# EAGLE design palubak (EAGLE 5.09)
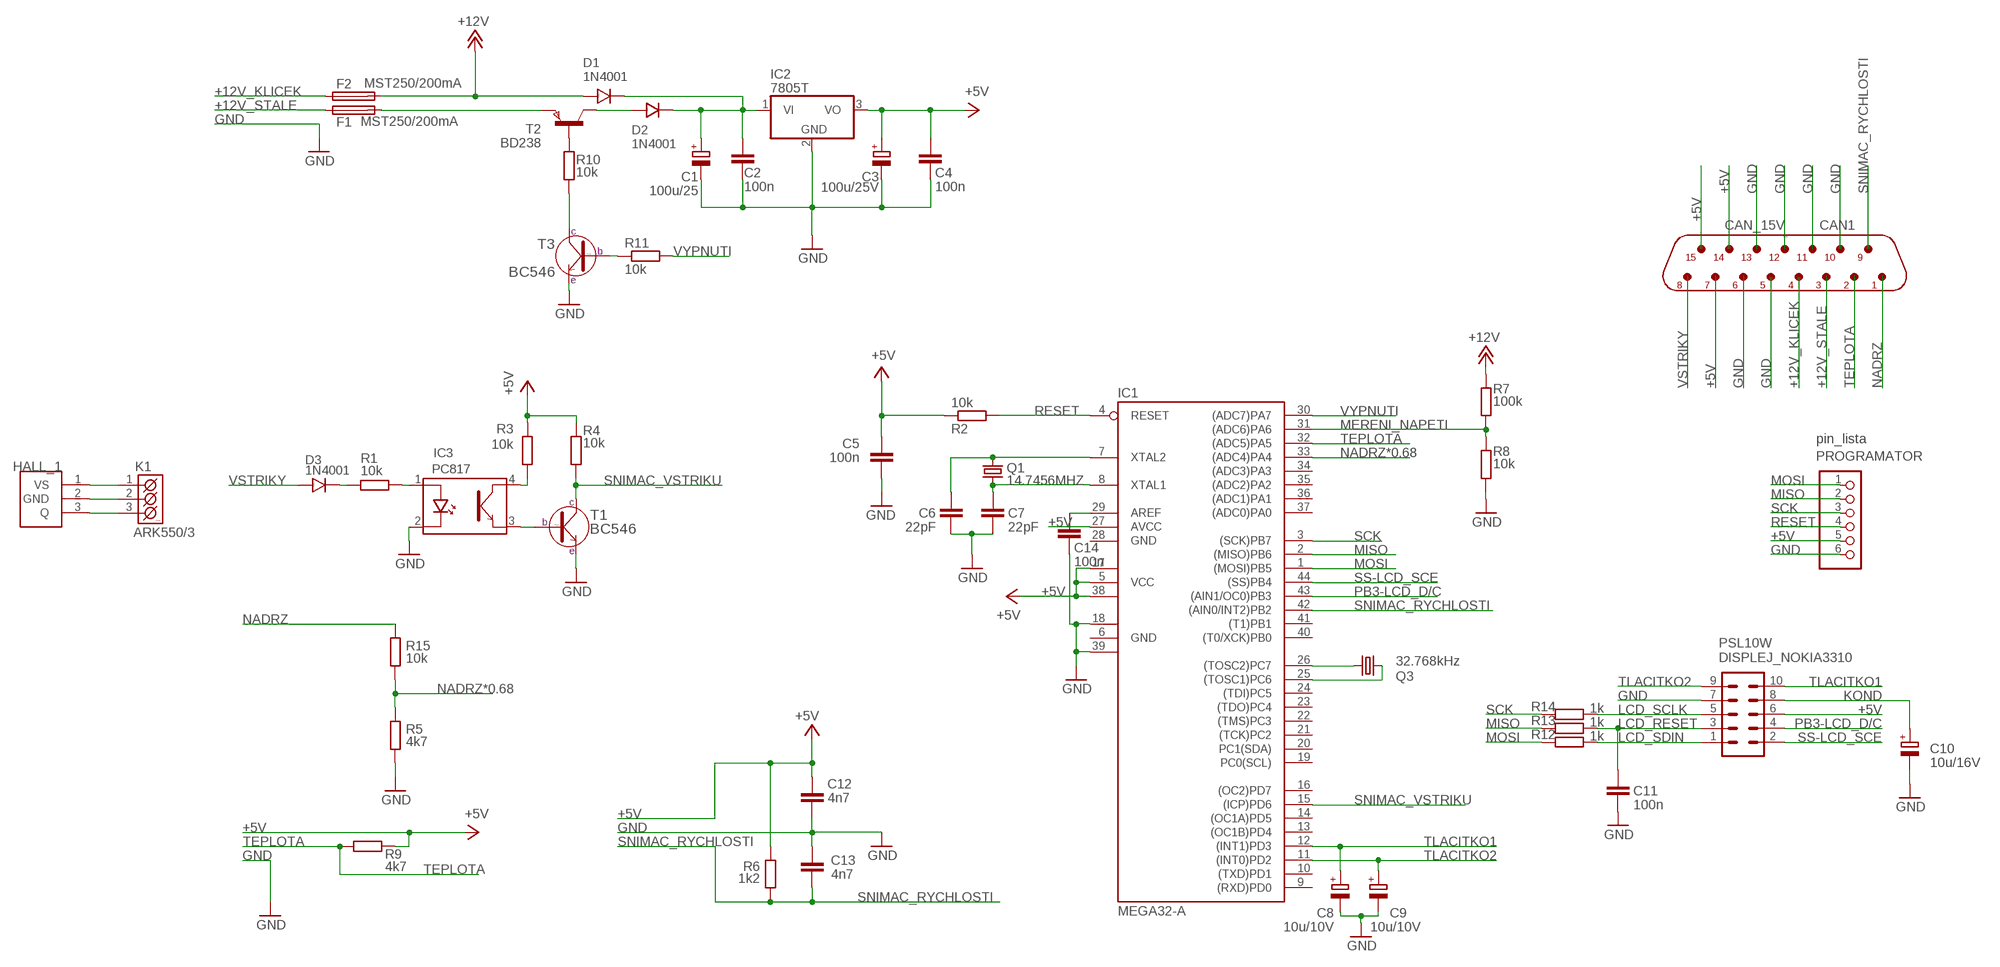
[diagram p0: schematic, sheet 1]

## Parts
C1  100u/25  CPOL-EUE3.5-8  [E3,5-8]
C2  100n  C-EUC1206  [C1206]
C3  100u/25V  CPOL-EUE3.5-8  [E3,5-8]
C4  100n  C-EUC1206  [C1206]
C5  100n  C-EUC1206  [C1206]
C6  22pF  C-EUC1206  [C1206]
C7  22pF  C-EUC1206  [C1206]
C8  10u/10V  CPOL-EUE2.5-6  [E2,5-6]
C9  10u/10V  CPOL-EUE2,5-6E  [E2,5-6E]
C10  10u/16V  CPOL-EUE2.5-6  [E2,5-6]
C11  100n  C-EUC1206  [C1206]
C12  4n7  C-EUC1206  [C1206]
C13  4n7  C-EUC1206  [C1206]
C14  100n  C-EUC1206  [C1206]
CAN1  CAN_15V  [CAN15V]
D1  1N4001  1N4007_SMD_SM-1  [SM-1]
D2  1N4001  1N4007_SMD_SM-1  [SM-1]
D3  1N4001  1N4007_SMD_SM-1  [SM-1]
DISPLEJ_NOKIA3310  PSL10W  10H  [10H]
F1  MST250/200mA  19560  [19560]
F2  MST250/200mA  19560  [19560]
HALL_1  TLE4905  [P-SSO-3-2]
IC1  MEGA32-A  [TQFP44]
IC2  7805T  [TO220H]
IC3  PC817  [DIL4]
K1  ARK550/3  [ARK550/3]
PROGRAMATOR  pin_lista  PINHD-1X6  [1X06]
Q1  14.7456MHZ  CRYTALHC49UP  [HC49UP@1]
Q3  32.768kHz  CRYSTALTC26H  [TC26H]
R1  10k  R-EU_M1206  [M1206]
R2  10k  R-EU_M1206  [M1206]
R3  10k  R-EU_M1206  [M1206]
R4  10k  R-EU_M1206  [M1206]
R5  4k7  R-EU_M1206  [M1206]
R6  1k2  R-EU_M1206  [M1206]
R7  100k  R-EU_M1206  [M1206]
R8  10k  R-EU_M1206  [M1206]
R9  4k7  R-EU_M1206  [M1206]
R10  10k  R-EU_M1206  [M1206]
R11  10k  R-EU_M1206  [M1206]
R12  1k  R-EU_M1206  [M1206]
R13  1k  R-EU_M1206  [M1206]
R14  1k  R-EU_M1206  [M1206]
R15  10k  R-EU_M1206  [M1206]
T1  BC546  [TO-92]
T2  BD238  [TO-126S]
T3  BC546  [TO-92]

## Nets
+5V: C3.+ C4.1 C5.2 C12.1 CAN1.7 CAN1.14 CAN1.15 DISPLEJ_NOKIA3310.6 IC1.5(VCC) IC1.17(VCC1) IC1.27(AVCC) IC1.38(VCC2) IC2.3(VO) PROGRAMATOR.5 R2.1 R3.1 R4.1 R6.1 R9.2
+12V: D1.A F2.2 R7.1
+12V_KLICEK: CAN1.4 F2.1
+12V_STALE: CAN1.3 F1.1
GND: C1.- C2.2 C3.- C4.2 C5.1 C6.2 C7.2 C8.- C9.- C10.- C11.2 C12.2 C13.1 C14.2 CAN1.5 CAN1.6 CAN1.10 CAN1.11 CAN1.12 CAN1.13 DISPLEJ_NOKIA3310.7 IC1.18(GND1) IC1.39(GND2) IC2.2(GND) IC3.2(K) PROGRAMATOR.6 R5.2 R8.2 T1.3(E) T3.3(E)
KOND: C10.+ DISPLEJ_NOKIA3310.8
LCD_RESET: C11.1 DISPLEJ_NOKIA3310.3 R13.1
LCD_SCLK: DISPLEJ_NOKIA3310.5 R14.1
LCD_SDIN: DISPLEJ_NOKIA3310.1 R12.1
MERENI_NAPETI: IC1.31((ADC6)PA6) R7.2 R8.1
MISO: IC1.2((MISO)PB6) PROGRAMATOR.2 R13.2
MOSI: IC1.1((MOSI)PB5) PROGRAMATOR.1 R12.2
N$1: C1.+ C2.1 D1.K D2.K IC2.1(VI)
N$2: D3.K R1.2
N$3: IC3.1(A) R1.1
N$4: IC3.4(C) R3.2
N$5: IC3.3(E) T1.2(B)
N$6: IC1.26((TOSC2)PC7) Q3.2
N$7: D2.A T2.2(C)
N$8: HALL_1.1(VS) K1.1(K1)
N$9: IC1.25((TOSC1)PC6) Q3.1
N$10: HALL_1.2(GND) K1.2(K2)
N$11: R10.1 T2.3(B)
N$12: R10.2 T3.1(C)
N$13: R11.1 T3.2(B)
N$14: HALL_1.3(Q) K1.3(K3)
N$19: F1.2 T2.1(E)
N$20: C14.1 IC1.29(AREF)
N$29: C7.1 IC1.8(XTAL1) Q1.1
NADRZ: CAN1.1 R15.1
NADRZ*0.68: IC1.33((ADC4)PA4) R5.1 R15.2
PB3-LCD_D/C: DISPLEJ_NOKIA3310.4 IC1.43((AIN1/OC0)PB3)
RESET: IC1.4(RESET) PROGRAMATOR.4 R2.2
SCK: IC1.3((SCK)PB7) PROGRAMATOR.3 R14.2
SNIMAC_RYCHLOSTI: C13.2 CAN1.9 IC1.42((AIN0/INT2)PB2) R6.2
SNIMAC_VSTRIKU: IC1.15((ICP)PD6) R4.2 T1.1(C)
SS-LCD_SCE: DISPLEJ_NOKIA3310.2 IC1.44((SS)PB4)
TEPLOTA: CAN1.2 IC1.32((ADC5)PA5) R9.1
TLACITKO1: C8.+ DISPLEJ_NOKIA3310.10 IC1.12((INT1)PD3)
TLACITKO2: C9.+ DISPLEJ_NOKIA3310.9 IC1.11((INT0)PD2)
VSTRIKY: CAN1.8 D3.A
VYPNUTI: IC1.30((ADC7)PA7) R11.2
XTAL1: C6.1 IC1.7(XTAL2) Q1.2
Unconnected: IC1.9((RXD)PD0) IC1.10((TXD)PD1) IC1.13((OC1B)PD4) IC1.14((OC1A)PD5) IC1.16((OC2)PD7) IC1.19(PC0(SCL)) IC1.20(PC1(SDA)) IC1.21((TCK)PC2) IC1.22((TMS)PC3) IC1.23((TDO)PC4) IC1.24((TDI)PC5) IC1.34((ADC3)PA3) IC1.35((ADC2)PA2) IC1.36((ADC1)PA1) IC1.37((ADC0)PA0) IC1.40((T0/XCK)PB0) IC1.41((T1)PB1)

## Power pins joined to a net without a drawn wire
GND: IC1.6(GND) IC1.28(GND)

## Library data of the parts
C1 C3 C8-C10 = rcl:CPOL-EU: POLARIZED CAPACITOR, European symbol
C2 C4-C7 C11-C14 = rcl:C-EU: CAPACITOR, European symbol
CAN1 = #PaJa_21:CAN_15V: Konektory CANNON - vidlice - 15pinu
D1-D3 = #PaJa_21:1N4007: Usmernovaci dioda - 1A, 1000V
DISPLEJ_NOKIA3310 = con-harting-h:10H: CONNECTOR
F1 F2 = fuse:19560: FUSE HOLDER
HALL_1 = #jedla:TLE4905
IC1 = atmel:MEGA32: MICROCONTROLLER 32 Kbytes FLASH 2 Kbytes SRAM 1 Kbytes EEPROM USART 8-channel 10 bit ADC Source: www.atmel.com .. doc2503.pdf
IC2 = linear:78*: Positive VOLTAGE REGULATOR Source: http://cache.national.com/ds/LM/LM78L05.pdf http://www.fairchildsemi.com/ds/LM/LM7805.pdf
IC3 = #PaJa_21:PC817: Optoclen
K1 = #PaJa_21:ARK550/3: Svorkovnice - roztec 3,5mm - trojita
PROGRAMATOR = pinhead:PINHD-1X6: PIN HEADER
Q1 = crystal:CRYTAL: CRYSTAL
Q3 = crystal:CRYSTAL: CRYSTAL
R1-R15 = rcl:R-EU_: RESISTOR, European symbol
T1 T3 = #PaJa_21:BC546: Tranzistor NPN - Univerzalni NF - Ic=0,1A
T2 = #_GM99:BD238

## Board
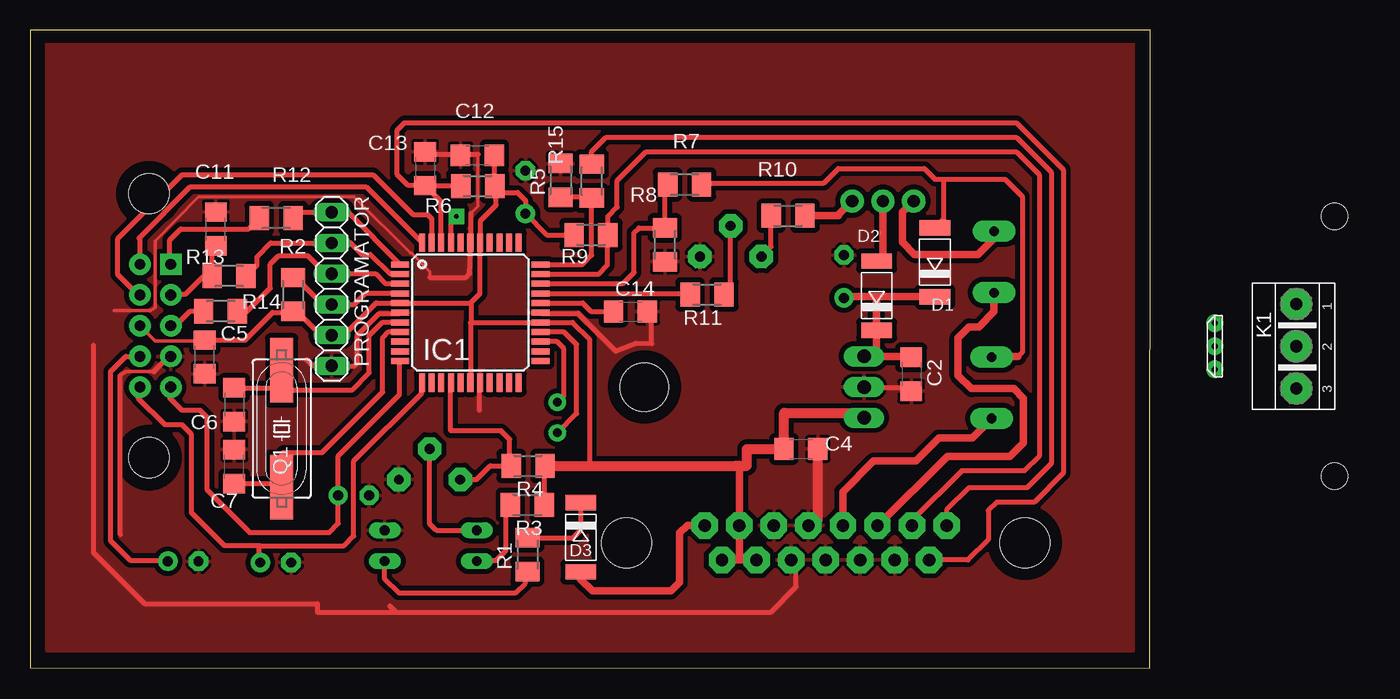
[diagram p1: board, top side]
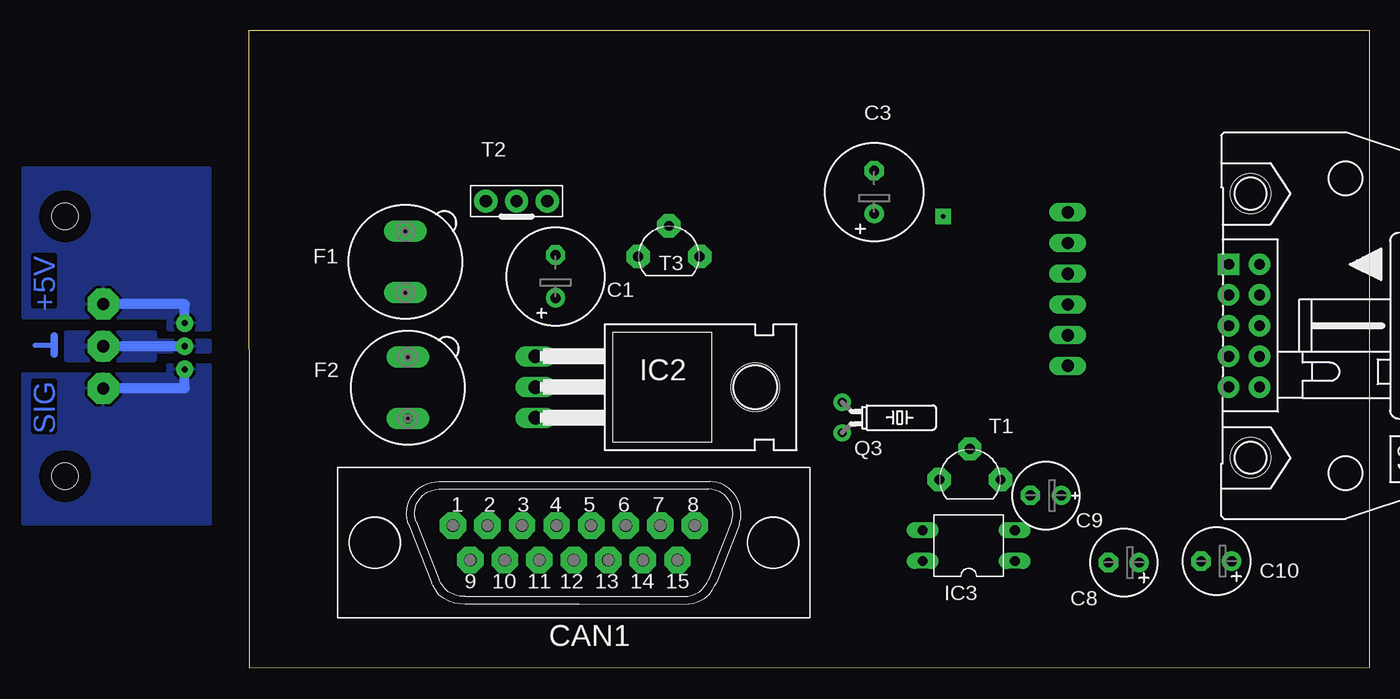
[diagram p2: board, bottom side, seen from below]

Size 92.65 x 52.8 mm. Coordinates in mm from the lower left corner, seen from the top.
Outline: 0,0.05 92.6,0 92.65,52.8 0,52.8 0,0.05
Copper layers (1*16): Top 0.035mm / dielectric 1.5mm / Bottom 0.035mm
Design rules "default": minimum track width 10mil, minimum drill 24mil, track to track 8mil, track to pad 8mil, pad to pad 8mil, via to via 8mil, smd to smd 8mil, copper to edge 40mil, drill to drill 8mil, minimum pad ring 10mil, minimum via ring 8mil, stop-mask expansion 4mil, vias tented up to drill 0mil, thermal gap 10mil
Holes 2.2 mm at 107.88,15.9 107.88,37.4

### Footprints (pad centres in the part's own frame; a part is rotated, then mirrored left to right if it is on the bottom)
E3,5-8 = drill 0.813 pad 1.6 round: + -1.778,0 | drill 0.813 pad 1.6 octagon: - 1.778,0
C1206 = smd 1.6 x 1.8: 1 -1.4,0; 2 1.4,0
E2,5-6 = drill 0.813 pad 1.6 round: + -1.27,0 | drill 0.813 pad 1.6 octagon: - 1.27,0
E2,5-6E = drill 0.813 pad 1.575 round: + -1.27,0 | drill 0.813 pad 1.575 octagon: - 1.27,0
CAN15V = drill 1.016 pad 2.184 octagon: 1 -9.842,1.27; 2 -6.985,1.27; 3 -4.128,1.27; 4 -1.27,1.27; 5 1.587,1.27; 6 4.445,1.27; 7 7.303,1.27; 8 10.16,1.27; 9 -8.414,-1.587; 10 -5.556,-1.587; 11 -2.699,-1.587; 12 0.159,-1.587; 13 3.016,-1.587; 14 5.874,-1.587; 15 8.731,-1.587 | hole 4.115: 16.637,-0.159; -16.32,-0.159
SM-1 = smd 1.27 x 2.54: A 2.857,0; K -2.857,0
10H = drill 0.9 pad 1.778 square: 1 -5.08,-1.27 | drill 0.9 pad 1.778 round: 2 -5.08,1.27; 3 -2.54,-1.27; 4 -2.54,1.27; 5 0,-1.27; 6 0,1.27; 7 2.54,-1.27; 8 2.54,1.27; 9 5.08,-1.27; 10 5.08,1.27 | hole 3.302: -10.922,0.533; 10.922,0.533
19560 = drill 0.813 pad 1.778 long: 1 -2.54,0; 2 2.54,0
P-SSO-3-2 = drill 0.5 pad 1.422 round: 1 1.905,0; 2 0,0; 3 -1.905,0
TQFP44 = smd 1.5 x 0.5: 1 -5.8,4; 2 -5.8,3.2; 3 -5.8,2.4; 4 -5.8,1.6; 5 -5.8,0.8; 6 -5.8,0; 7 -5.8,-0.8; 8 -5.8,-1.6; 9 -5.8,-2.4; 10 -5.8,-3.2; 11 -5.8,-4; 23 5.8,-4; 24 5.8,-3.2; 25 5.8,-2.4; 26 5.8,-1.6; 27 5.8,-0.8; 28 5.8,0; 29 5.8,0.8; 30 5.8,1.6; 31 5.8,2.4; 32 5.8,3.2; 33 5.8,4 | smd 0.5 x 1.5: 12 -4,-5.8; 13 -3.2,-5.8; 14 -2.4,-5.8; 15 -1.6,-5.8; 16 -0.8,-5.8; 17 0,-5.8; 18 0.8,-5.8; 19 1.6,-5.8; 20 2.4,-5.8; 21 3.2,-5.8; 22 4,-5.8; 34 4,5.8; 35 3.2,5.8; 36 2.4,5.8; 37 1.6,5.8; 38 0.8,5.8; 39 0,5.8; 40 -0.8,5.8; 41 -1.6,5.8; 42 -2.4,5.8; 43 -3.2,5.8; 44 -4,5.8
TO220H = drill 1.118 long: 1 -2.54,-13.335; 2 0,-13.335; 3 2.54,-13.335 | hole 4: 0,4.826
DIL4 = drill 0.813 pad 1.27 long: 1 -1.27,-3.81; 2 1.27,-3.81; 3 1.27,3.81; 4 -1.27,3.81
ARK550/3 = drill 1.016 pad 2.54 octagon: 1 -3.493,0; 2 0,0; 3 3.493,0
1X06 = drill 1.016 long: 1 -6.35,0; 2 -3.81,0; 3 -1.27,0; 4 1.27,0; 5 3.81,0; 6 6.35,0
HC49UP@1 = smd 5.334 x 1.93: 1 -4.826,0; 2 4.826,0
TC26H = drill 0.7 pad 1.422 round: 1 -1.27,0; 2 1.27,0
M1206 = smd 1.6 x 2: 1 -1.4,0; 2 1.4,0
TO-92 = drill 0.813 pad 1.93 octagon: 1 0,2.54; 2 2.54,0; 3 0,-2.54
TO-126S = drill 1.016 pad 1.93 round: 1 0,0; 2 2.54,0; 3 5.08,0

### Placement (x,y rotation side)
C1  67.31,32.43 90 bottom
C2  72.87,24.33 270 top
C3  40.95,39.41 90 bottom
C4  63.75,18.15 0 top
C5  14.43,25.77 90 top
C6  16.86,21.82 270 top
C7  16.88,16.7 90 top
C8  20.3,8.75 180 bottom
C9  26.75,14.3 180 bottom
C10  12.65,8.86 180 bottom
C11  15.35,36.35 90 top
C12  36.99,42.44 180 top
C13  32.66,41.34 270 top
C14  49.65,29.52 0 top
CAN1  65.95,10.55 0 bottom
D1  74.83,33.6 90 top
D2  70.01,30.85 90 top
D3  45.54,10.85 270 top
DISPLEJ_NOKIA3310  10.35,28.35 270 bottom
F1  79.73,33.62 90 bottom
F2  79.53,23.21 90 bottom
HALL_1  97.98,26.65 90 top  (outside the outline)
IC1  36.4,29.43 0 top
IC2  55.63,23.28 270 bottom
IC3  33.13,10.15 90 bottom
K1  104.73,26.65 270 top  (outside the outline)
PROGRAMATOR  24.94,31.38 270 top
Q1  20.8,19.83 90 top
Q3  43.6,20.75 270 bottom
R1  41.13,9.41 90 top
R2  21.74,30.93 90 top
R3  41.11,13.53 180 top
R4  41.18,16.75 180 top
R5  43.88,40.38 90 top
R6  37.02,39.9 180 top
R7  54.13,40.04 180 top
R8  52.5,35.04 270 top
R9  46.39,35.86 180 top
R10  62.69,37.45 180 top
R11  55.98,30.94 180 top
R12  20.35,37.25 0 top
R13  16.45,32.45 0 top
R14  15.75,29.55 0 top
R15  46.44,40.32 270 top
T1  33.03,15.62 90 bottom
T2  73.07,38.66 0 bottom
T3  57.93,34.08 90 bottom

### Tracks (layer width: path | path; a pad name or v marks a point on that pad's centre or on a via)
+5V
  Top 0.254: R6.1 38.04,39.71 | 58.36,16.75 58.36,16.85
  Top 0.305: DISPLEJ_NOKIA3310.6 10.33,27.1 14.26,27.1
  Top 0.406: IC1.27 | IC1.27 42.18,28.6 36.4,28.6 | IC1.27 44.87,28.63 46.25,27.25 46.25,16.75 43.35,16.75 R4.1 42.51,16.69 R3.1 | 38.94,39.37 R6.1 38.39,39.93 C12.1 | 38.94,39.37 38.55,39.37 38.55,38.35 37.25,37.05 37.25,35.23 IC1.38 37.2,31 36.45,30.25 | 36.4,28.6 IC1.17 | 36.45,30.25 36.45,28.65 36.4,28.6 | 36.45,30.25 36.43,30.23 IC1.5 28.65,30.23 28.65,30.25 25.97,27.57 PROGRAMATOR.5 24.03,27.57 22.65,28.95 22.32,28.95 R2.1 21.66,29.45 20.05,29.45 17.77,27.17 C5.2 | 13.85,26.95 14.21,26.95 C5.2 | 14.26,27.1 C5.2 | R9.2 42.72,35.86 C3.+ 40.99,37.63 40.99,38.7 40.32,39.37 38.94,39.37
  Top 0.61: 58.65,16.75 CAN1.7 58.65,9.01 58.6,8.96 | 58.6,8.96 CAN1.15 | 58.6,8.96 CAN1.14
  Top 0.813: IC2.3 68.86,21.15 62.35,21.15 C4.1 59.27,18.15 59.27,16.75 58.65,16.75 58.36,16.75 43.35,16.75
+12V
  Top 0.406: 81.7,25.8 82.05,26.15 82.05,39.05 80.63,40.47 75.55,40.47 | R7.1 55.64,40.15 65.65,40.15 66.85,41.35 73.95,41.35 74.83,40.47 75.55,40.47 | D1.A 75.55,37.18 75.55,40.47
  Top 0.61: 81.7,25.8 79.58,25.8 F2.2
+12V_KLICEK
  Top 0.61: CAN1.4 67.22,14.62 69.75,17.15 73.25,17.15 75.15,19.05 77.91,19.05 F2.1
+12V_STALE
  Top 0.61: CAN1.3 70.12,11.82 75.85,17.55 81.05,17.55 82.15,18.65 82.15,22.35 81.35,23.15 77.85,23.15 76.75,24.25 76.75,27.35 77.65,28.25 78.45,28.25 79.73,29.53 F1.1
GND
  Top 0.254: 33.05,32.35 33.05,32.85 31.55,34.35 | 36.45,37.65 37.05,38.25 37.05,42.52 | 31.45,34.35 26.75,39.05 13.95,39.05 10.35,35.35
  Top 0.305: 31.45,34.35 31.55,34.35 | 7.45,24.26 7.94,24.55 10.2,24.55 10.3,24.5 | 10.35,35.35 10.35,29.85 9.95,29.6 6.95,29.6
  Top 0.406: 33.05,32.35 36.05,32.35 36.35,32.65 36.45,35.18 IC1.39 36.45,35.27 36.45,37.65 | 63.35,8.66 63.35,6.75 61.25,4.65 30.25,4.65 | C13.1 32.88,42.52 37.05,42.52 | IC1.6 30.52,29.35 28.85,29.35 27.05,27.55 27.05,25.25 26.83,25.03 PROGRAMATOR.6 24.27,25.03 24.25,25.05 23.35,25.05 22.85,25.55 | 30.25,4.65 29.76,5.14 | 30.25,4.65 23.75,4.65 23.75,5.35 9.45,5.35 5.25,9.55 5.25,26.75 | 7.45,11.05 7.45,24.26 | IC2.2 69.34,23.25 72.55,23.25 | DISPLEJ_NOKIA3310.7 11.46,25.81 10.2,24.55 | IC1.18 37.15,23.63 37.15,21.35 | IC1.28 42.26,29.38 45.33,29.38 48.41,26.25 50.14,26.91 51.4,26.86 51.4,29.17 C14.2
  Top 0.813: 65.15,12.25 C4.2
  pour Top (isolate 0.406): 1.35,1.45 91.25,1.45 91.25,51.95 1.35,51.95
KOND
  Top 0.406: DISPLEJ_NOKIA3310.8 7.91,25.81 6.65,24.55 6.65,10.55 8.26,8.94 11.3,8.94 C10.+
LCD_RESET
  Top 0.406: DISPLEJ_NOKIA3310.3 11.68,30.95 12.85,30.95 14.35,32.45 R13.1 15.05,34.65 C11.1
LCD_SCLK
  Top 0.406: DISPLEJ_NOKIA3310.5 12.05,28.35 13.25,29.55 R14.1
LCD_SDIN
  Top 0.406: DISPLEJ_NOKIA3310.1 11.55,33.5 11.55,35.45 12.45,36.35 18.05,36.35 R12.1
MERENI_NAPETI
  Top 0.406: IC1.31 42.22,31.85 49.05,31.85 49.95,32.75 49.95,36.05 50.34,36.44 R8.1 52.5,39.81 R7.2
MISO
  Top 0.406: IC1.2 30.58,32.65 29.75,32.65 28.15,34.25 27.45,34.25 26.51,35.19 PROGRAMATOR.2 19.89,35.19 18.75,34.05 18.75,33.35 R13.2
MOSI
  Top 0.406: IC1.1 26.3,37.73 PROGRAMATOR.1 22.23,37.73 R12.2
N$1
  Top 0.61: C2.1 72.79,25.82 IC2.1 70.01,25.82 D2.K 70.01,30.65 70.1,30.74 | 70.1,30.74 67.4,30.74 C1.+ | 70.1,30.74 D1.K
N$2
  Top 0.406: R1.2 44.91,10.81 45.55,11.45 45.55,13.69 D3.K
N$3
  Top 0.406: R1.1 40.95,7.84 40.95,7.05 40.15,6.25 30.45,6.25 29.32,7.38 IC3.1
N$4
  Top 0.406: IC3.4 37.01,8.95 38.55,8.95 39.35,9.75 39.35,13.17 R3.2
N$5
  Top 0.406: T1.2 33.05,18.14 33.05,11.95 33.58,11.42 IC3.3
N$6
  Top 0.406: Q3.2 45.2,21.08 45.2,26.8 44.17,27.83 IC1.26
N$7
  Top 0.61: D2.A 70.53,33.7 T2.2
N$8
  Bottom 0.813: HALL_1.1 97.98,30.14 K1.1
  pour Bottom: 111.38,41.4 111.38,29.02 99.38,29.02 99.38,28.02 95.88,28.02 95.88,41.4
N$9
  Top 0.406: IC1.25 43.57,27.03 44.15,26.45 44.15,22.52 44.1,22.52 Q3.1
N$10
  Bottom 0.813: HALL_1.2 K1.2
  pour Bottom: 107.75,25.52 107.75,27.77 100.5,27.77 100.5,25.52
  pour Bottom: 100.38,27.4 100.38,27.15 95.88,27.15 95.88,26.15 100.5,26.15 100.5,27.4
N$11
  Top 0.61: R10.1 66.86,37.45 66.86,37.52 T2.3
N$12
  Top 0.406: T3.1 61.29,34.89 R10.2
N$13
  Top 0.406: R11.1 57.93,30.94 T3.2
N$14
  Bottom 0.813: HALL_1.3 97.98,23.16 K1.3
  pour Bottom (rank 6): 111.38,11.9 111.38,24.4 99.38,24.4 99.38,25.15 95.88,25.15 95.88,11.9
N$15
  Bottom 0.406: 110.35,26.75 108.85,26.75
N$16
  Bottom 0.61: 108.79,26 108.79,27.5
N$17  (via drill 0.4 pad 1.27)
  other vias: 35.25,37.4
N$18
  Top 0.406: 34.8,34.99 34.81,34.99 34.81,37.57
N$19
  Top 0.61: T2.1 72.15,37.74 72.15,35.25 73.15,34.25 78.4,34.25 79.73,35.58 F1.2
N$20
  Top 0.406: C14.1 46.4,29.52 45.7,30.23 IC1.29
N$29
  Top 0.406: IC1.8 30.58,27.85 29.65,27.85 29.15,27.35 29.15,22.85 24.15,17.85 20.95,17.85 20.8,17.7 Q1.1 20.5,15.3 C7.1
NADRZ
  Top 0.406: CAN1.1 75.79,13.09 77.65,14.95 82.45,14.95 84.45,16.95 84.45,41.05 81.55,43.95 47.64,43.95 46.44,42.75 R15.1
NADRZ*0.68
  Top 0.406: R5.1 46.39,38.98 R15.2 46.44,34.18 45.69,33.43 IC1.33
PB3-LCD_D/C
  Top 0.406: IC1.43 33.2,37.2 32.85,37.55 31.65,37.55 28.35,40.85 12.55,40.85 7.25,35.55 7.25,32.56 8.92,30.89 DISPLEJ_NOKIA3310.4
RESET
  Top 0.406: IC1.4 30.58,31.05 27.75,31.05 26.81,30.11 PROGRAMATOR.4 24.19,30.11 22.55,31.75 22.32,31.75 R2.2
SCK
  Top 0.406: IC1.3 30.58,31.85 29.35,31.85 28.55,32.65 PROGRAMATOR.3 24.45,32.65 22.95,34.15 20.55,34.15 19.85,33.45 19.85,31.45 17.95,29.55 R14.2
SNIMAC_RYCHLOSTI
  Top 0.406: C13.2 34,38.6 IC1.42 | C13.2 31.26,39.94 30.35,40.85 30.35,44.55 30.95,45.15 81.55,45.15 85.45,41.25 85.45,16.15 83.05,13.75 79.95,13.75 79.25,13.05 79.25,10.65 77.56,8.96 CAN1.9 | C13.2 35.57,39.94 R6.2
SNIMAC_VSTRIKU
  Top 0.406: IC1.15 34.78,23.61 34.78,19.65 38.95,19.65 39.65,18.95 39.65,16.88 R4.2 | R4.2 39.59,16.95 | T1.1 36.92,15.62 38.05,16.75 R4.2
SS-LCD_SCE
  Top 0.406: IC1.44 27.78,39.85 13.25,39.85 9,35.6 9.08,35.6 DISPLEJ_NOKIA3310.2
TEPLOTA
  Top 0.406: IC1.32 47.03,32.63 47.75,33.35 47.75,35.83 R9.1 47.79,37.38 48.55,38.15 48.55,40.35 50.95,42.75 81.55,42.75 83.45,40.85 83.45,17.55 82.25,16.35 77.05,16.35 72.94,12.24 CAN1.2
TLACITKO1
  Top 0.254: C8.+ 18.99,9.23 18.95,9.23
  Top 0.406: 32.4,23.49 IC1.12 | 32.4,23.49 | 8.95,23.15 8.9,23.1 9.15,22.85 | 32.4,23.49 32.4,22.8 26.75,17.15 26.75,10.95 25.95,10.15 19,10.15 | 8.95,23.15 8.95,22.35 11.15,20.15 12.55,20.15 13.35,19.35 13.35,12.88 16.08,10.15 19,10.15 | DISPLEJ_NOKIA3310.10 8.96,23.15 8.95,23.15 | 18.95,8.58 18.95,9.23 18.95,10.1 19,10.15
TLACITKO2
  Top 0.406: IC1.11 30.55,25.38 30.55,22.65 25.48,17.58 C9.+ 25.48,11.98 24.75,11.25 18.15,11.25 14.65,14.75 14.65,20.75 14.05,21.35 12.55,21.35 11.54,22.36 11.62,22.44 DISPLEJ_NOKIA3310.9
VSTRIKY
  Top 0.61: D3.A 45.54,7.36 46.5,6.4 53,6.4 53.7,7.1 53.7,11.2 54.35,11.85 55.76,11.85 CAN1.8
VYPNUTI
  Top 0.406: IC1.30 54.58,31.03 R11.2
XTAL1
  Top 0.406: IC1.7 30.55,28.57 30.47,28.65 29.15,28.65 28.05,27.55 28.05,24.45 26.65,23.05 20.8,23.05 | 20.8,23.45 20.8,23.05 | 20.8,23.45 Q1.2 | 20.8,23.05 20.8,22.5 | 20.8,23.45 20.57,23.22 C6.1

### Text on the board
Bottom: +5V | SIG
